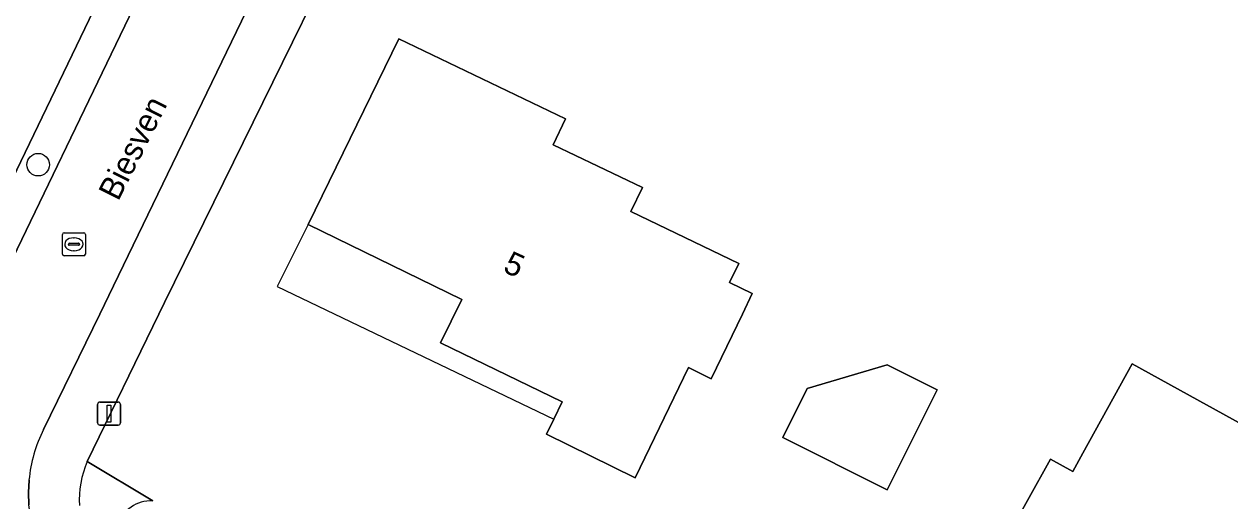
# Model space of a CAD drawing. Extents: x 163426 to 164192, y 380329 to 381641.
# Drawn here: x 163745.4 to 163797.6, y 381491.9 to 381512.6 of the extents above; entities that cross this region are included whole.
import ezdxf

# ---------------------------------------------------------------- set-up
doc = ezdxf.new("R2010")
doc.units = 0
for name, color, linetype in [('IMGEO_Boom', 7, 'Continuous'), ('IMGEO_Erf', 7, 'Continuous'), ('IMGEO_Groenvoorziening', 7, 'Continuous'), ('IMGEO_Kolk', 7, 'Continuous'), ('IMGEO_Lichtmast', 7, 'Continuous'), ('IMGEO_Oever', 7, 'Continuous'), ('IMGEO_Openbare_ruimte_label', 7, 'Continuous'), ('IMGEO_Pand', 7, 'Continuous'), ('IMGEO_Pand_nummerreeks', 7, 'Continuous'), ('IMGEO_Pand_overbouw', 7, 'Continuous'), ('IMGEO_Rijbaan_lokaal_open', 7, 'Continuous'), ('IMGEO_Voetpad_open', 7, 'Continuous')]:
    doc.layers.add(name, color=color, linetype=linetype)

msp = doc.modelspace()

# ---------------------------------------------------------------- linework, layer by layer
at = {"layer": 'IMGEO_Boom'}
msp.add_circle((163745.966, 381506.482), 0.489, dxfattribs=at)
at = {"layer": 'IMGEO_Erf'}
for points in [[(163709.885, 381513.746), (163716.69, 381510.952), (163720.442, 381509.517), (163742.008, 381500), (163742.257, 381500.486), (163755.555, 381528.169)], [(163763.393, 381524.85), (163751.446, 381500.501), (163751.203, 381500), (163748.094, 381493.596), (163750.929, 381491.888)]]:
    msp.add_lwpolyline(points, dxfattribs=at)
for points in [[(163771.846, 381492.891), (163768.002, 381494.78), (163768.316, 381495.43), (163768.679, 381496.182), (163763.41, 381498.748), (163764.329, 381500.636), (163757.668, 381503.881), (163761.598, 381511.951), (163768.828, 381508.473), (163768.288, 381507.343), (163772.167, 381505.491), (163771.659, 381504.45), (163776.349, 381502.199), (163775.94, 381501.374), (163776.927, 381500.885), (163776.501, 381500), (163775.149, 381497.192), (163774.155, 381497.672)], [(163782.774, 381492.375), (163778.245, 381494.64), (163779.308, 381496.765), (163782.779, 381497.788), (163784.941, 381496.707)], [(163803.067, 381492.504), (163811.499, 381494.802), (163813.345, 381493.772), (163809.346, 381486.611), (163807.601, 381487.585), (163804.327, 381489.413), (163802.092, 381485.365), (163799.674, 381480.988), (163796.223, 381482.916), (163794.699, 381483.768), (163793.607, 381481.84), (163790.365, 381483.728), (163789.888, 381482.953), (163786.211, 381484.952), (163788.823, 381489.583), (163787.861, 381490.119), (163789.86, 381493.705), (163790.822, 381493.169), (163791.261, 381493.956), (163793.398, 381497.833)]]:
    msp.add_lwpolyline(points, close=True, dxfattribs=at)
at = {"layer": 'IMGEO_Groenvoorziening'}
msp.add_lwpolyline([(163750.929, 381491.888), (163748.094, 381493.596)], dxfattribs=at)
for centre, radius, start, end in [((163751.895, 381491.927), 4.151, 156.2975, 183.3723), ((163750.847, 381490.382), 1.508, 86.8822, 162.3747)]:
    msp.add_arc(centre, radius, start, end, dxfattribs=at)
at = {"layer": 'IMGEO_Kolk'}
for p, q in [((163747.015, 381502.603), (163747.015, 381503.455)), ((163747.09, 381503.529), (163747.942, 381503.529)), ((163747.503, 381503.309), (163747.528, 381503.309)), ((163748.016, 381503.455), (163748.016, 381502.603)), ((163747.274, 381503.023), (163747.274, 381503.035)), ((163747.712, 381502.986), (163747.314, 381502.986)), ((163747.317, 381503.072), (163747.715, 381503.072)), ((163747.526, 381502.749), (163747.501, 381502.749)), ((163747.758, 381503.035), (163747.758, 381503.023)), ((163747.942, 381502.529), (163747.09, 381502.529))]:
    msp.add_line(p, q, dxfattribs=at)
for points in [[(163747.015, 381502.603), (163747.015, 381503.455)], [(163747.09, 381503.529), (163747.942, 381503.529)], [(163748.016, 381503.455), (163748.016, 381502.603)], [(163747.942, 381502.529), (163747.09, 381502.529)]]:
    msp.add_lwpolyline(points, dxfattribs=at)
for centre, radius, start, end in [((163747.092, 381503.453), 0.0765, 91.552, 178.448), ((163747.092, 381503.453), 0.0765, 91.552, 178.448), ((163747.94, 381503.453), 0.0765, 1.552, 88.448), ((163747.94, 381503.453), 0.0765, 1.552, 88.448), ((163747.314, 381503.032), 0.0403, 85.8775, 175.7526), ((163747.311, 381503.022), 0.0366, 178.938, 274.7102), ((163747.715, 381503.029), 0.043, 264.8664, 352.4533), ((163747.719, 381503.034), 0.0386, 1.7309, 96.639), ((163747.092, 381502.605), 0.0765, 181.552, 268.448), ((163747.092, 381502.605), 0.0765, 181.552, 268.448), ((163747.94, 381502.605), 0.0765, 271.552, 358.448), ((163747.94, 381502.605), 0.0765, 271.552, 358.448)]:
    msp.add_arc(centre, radius, start, end, dxfattribs=at)
for centre, major_axis, ratio, start_param, end_param in [((163747.502, 381503.029), (-0.387, 0.002), 0.722429, 4.712389, 7.853982), ((163747.527, 381503.029), (-0.39, 0.002), 0.717154, 1.570796, 4.712389)]:
    msp.add_ellipse(centre, major_axis=major_axis, ratio=ratio, start_param=start_param, end_param=end_param, dxfattribs=at)
at = {"layer": 'IMGEO_Lichtmast'}
for p, q in [((163748.542, 381495.276), (163748.542, 381496.076)), ((163748.542, 381496.076), (163748.542, 381495.276)), ((163748.642, 381496.176), (163749.432, 381496.176)), ((163749.432, 381496.176), (163748.642, 381496.176)), ((163749.532, 381496.076), (163749.532, 381495.276)), ((163749.532, 381495.276), (163749.532, 381496.076)), ((163749.432, 381495.176), (163748.642, 381495.176)), ((163748.642, 381495.176), (163749.432, 381495.176))]:
    msp.add_line(p, q, dxfattribs=at)
msp.add_lwpolyline([(163748.962, 381496.051), (163749.112, 381496.051), (163749.112, 381495.301), (163748.962, 381495.301), (163748.962, 381496.051)], dxfattribs=at)
for centre, start, end in [((163748.642, 381496.076), 90, 180), ((163748.642, 381496.076), 90, 180), ((163749.432, 381496.076), 0, 90), ((163749.432, 381496.076), 360, 90), ((163748.642, 381495.276), 180, 270), ((163748.642, 381495.276), 180, 270), ((163749.432, 381495.276), 270, 0), ((163749.432, 381495.276), 270, 0)]:
    msp.add_arc(centre, 0.1, start, end, dxfattribs=at)
at = {"layer": 'IMGEO_Oever'}
msp.add_arc((163750.847, 381490.382), 1.508, 86.8822, 162.3747, dxfattribs=at)
at = {"layer": 'IMGEO_Pand'}
for points in [[(163771.659, 381504.45), (163772.167, 381505.491), (163768.288, 381507.343), (163768.828, 381508.473), (163761.598, 381511.951), (163757.668, 381503.881), (163764.329, 381500.636), (163763.41, 381498.748), (163768.679, 381496.182), (163768.316, 381495.43), (163768.002, 381494.78), (163771.846, 381492.891), (163774.155, 381497.672), (163775.149, 381497.192), (163776.501, 381500), (163776.927, 381500.885), (163775.94, 381501.374), (163776.349, 381502.199)], [(163782.774, 381492.375), (163784.941, 381496.707), (163782.779, 381497.788), (163779.308, 381496.765), (163778.245, 381494.64)], [(163793.607, 381481.84), (163794.699, 381483.768), (163796.223, 381482.916), (163799.674, 381480.988), (163802.092, 381485.365), (163804.327, 381489.413), (163807.601, 381487.585), (163809.346, 381486.611), (163813.345, 381493.772), (163811.499, 381494.802), (163803.067, 381492.504), (163793.398, 381497.833), (163791.261, 381493.956), (163790.822, 381493.169), (163789.86, 381493.705), (163787.861, 381490.119), (163788.823, 381489.583), (163786.211, 381484.952), (163789.888, 381482.953), (163790.365, 381483.728)]]:
    msp.add_lwpolyline(points, close=True, dxfattribs=at)
at = {"layer": 'IMGEO_Pand_overbouw'}
msp.add_lwpolyline([(163757.668, 381503.881), (163756.329, 381501.196), (163768.316, 381495.43), (163768.679, 381496.182), (163763.41, 381498.748), (163764.329, 381500.636)], close=True, dxfattribs=at)
at = {"layer": 'IMGEO_Rijbaan_lokaal_open'}
for points in [[(163756.899, 381527.435), (163743.677, 381500), (163743.604, 381499.848), (163743.1, 381498.851), (163742.315, 381497.297)], [(163746.201, 381494.982), (163748.64, 381500), (163749.235, 381501.225), (163760.744, 381525.086)], [(163733.515, 381494.261), (163748.812, 381486.917), (163748.665, 381486.994), (163748.207, 381487.271), (163747.776, 381487.588), (163747.374, 381487.942), (163747.006, 381488.33), (163746.673, 381488.75), (163746.38, 381489.197), (163746.128, 381489.67), (163745.919, 381490.162), (163745.754, 381490.672), (163745.636, 381491.194), (163745.566, 381491.725), (163745.542, 381492.259), (163745.567, 381492.794)]]:
    msp.add_lwpolyline(points, dxfattribs=at)
msp.add_arc((163751.537, 381492.25), 5.995, 152.8875, 174.7933, dxfattribs=at)
at = {"layer": 'IMGEO_Voetpad_open'}
for points in [[(163755.555, 381528.169), (163742.257, 381500.486), (163742.008, 381500), (163740.842, 381497.724)], [(163742.315, 381497.297), (163743.1, 381498.851), (163743.604, 381499.848), (163743.677, 381500), (163756.899, 381527.435)], [(163760.744, 381525.086), (163749.235, 381501.225), (163748.64, 381500), (163746.201, 381494.982)], [(163748.094, 381493.596), (163751.203, 381500), (163751.446, 381500.501), (163763.393, 381524.85)], [(163745.567, 381492.794), (163745.542, 381492.259), (163745.566, 381491.725)]]:
    msp.add_lwpolyline(points, dxfattribs=at)
for centre, radius, start, end in [((163751.537, 381492.25), 5.995, 152.8875, 174.7933), ((163751.895, 381491.927), 4.151, 156.2975, 183.3723)]:
    msp.add_arc(centre, radius, start, end, dxfattribs=at)

# ---------------------------------------------------------------- texts
at = {"layer": 'IMGEO_Openbare_ruimte_label'}
msp.add_text('Biesven', height=1, rotation=63.1275, dxfattribs=at).set_placement((163749.432, 381504.865))
at = {"layer": 'IMGEO_Pand_nummerreeks'}
msp.add_text('5', height=1, rotation=335.3456, dxfattribs=at).set_placement((163766.071, 381501.859))

doc.saveas('drawing.dxf')
